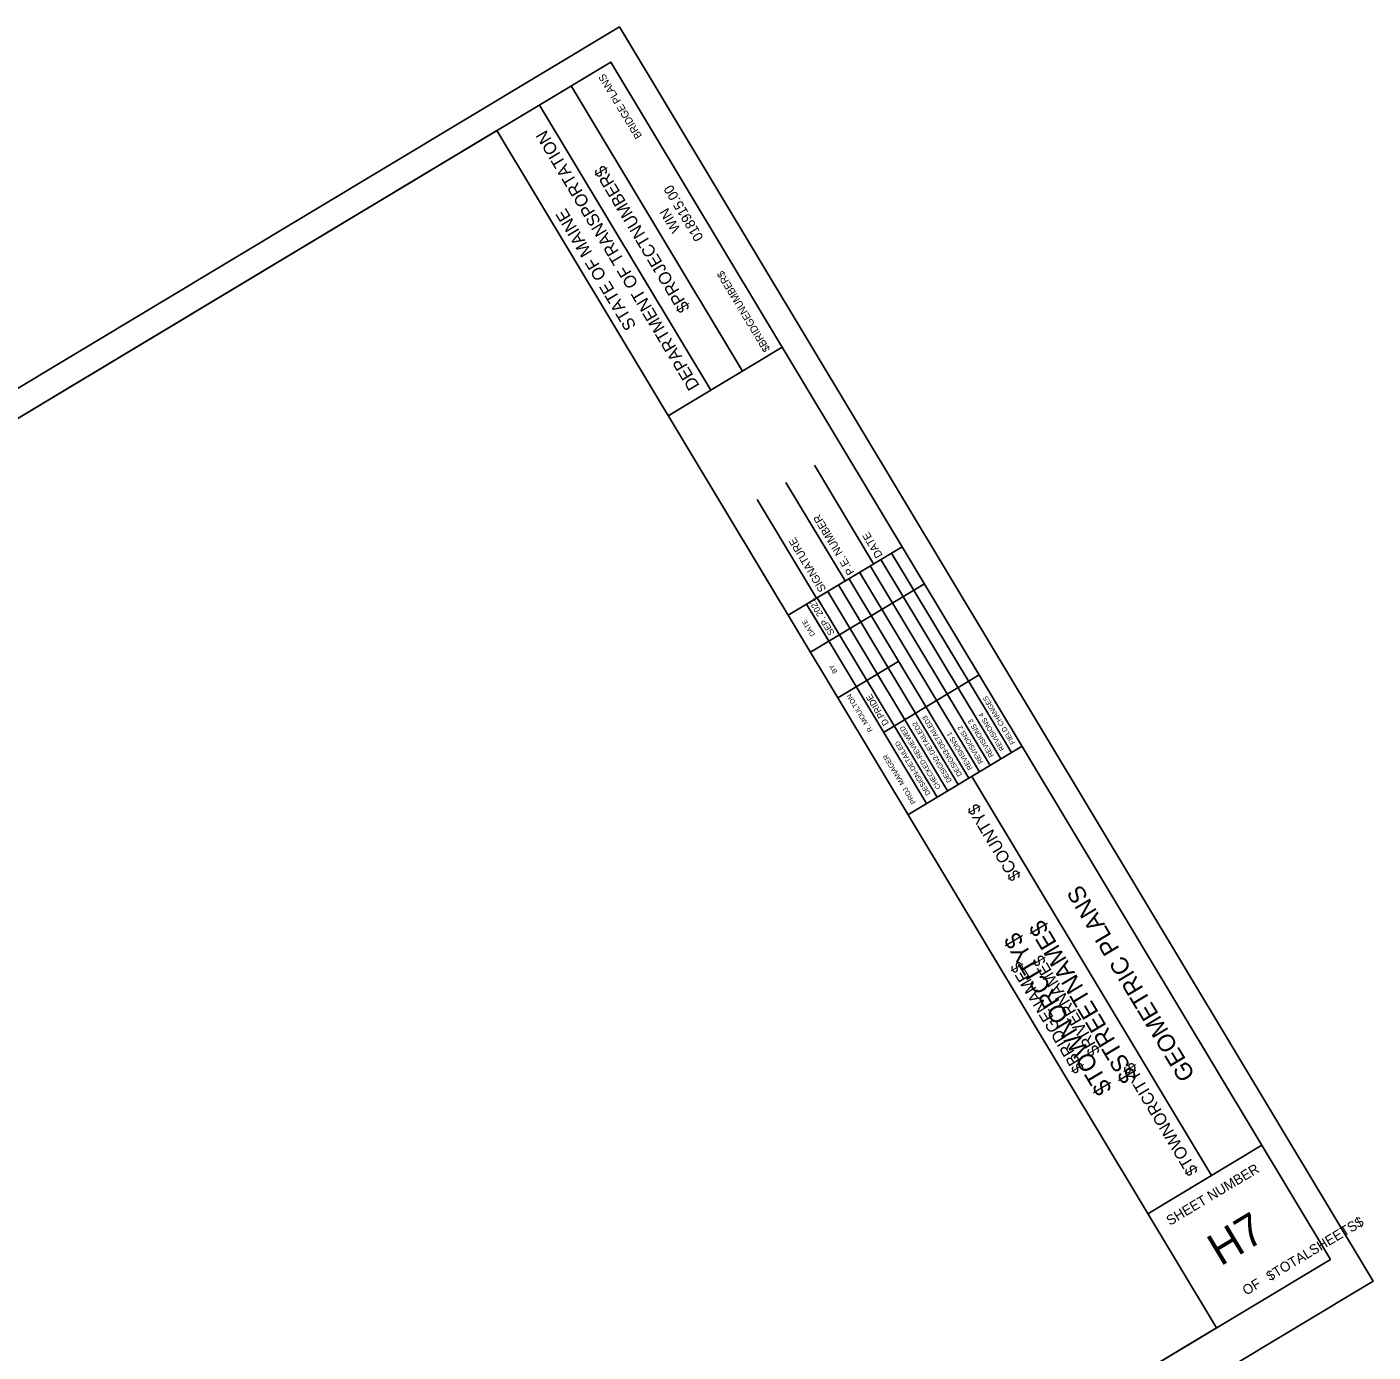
# Model space of a CAD drawing. Extents: x 1745684 to 1746696, y 463699 to 464609.
# Drawn here: x 1746190 to 1746696, y 464110 to 464609 of the extents above; entities that cross this region are included whole.
import ezdxf

# ---------------------------------------------------------------- set-up
doc = ezdxf.new("R2010")
doc.units = 0
for name, color, linetype in [('ANNOTATION', 7, 'Continuous'), ('D_Roadway_Centerline_Flags', 7, 'Continuous'), ('DIMENSIONS', 7, 'Continuous'), ('M_Fencing', 7, 'Continuous'), ('M_Misc_MiscItems', 7, 'Continuous')]:
    doc.layers.add(name, color=color, linetype=linetype)

msp = doc.modelspace()

# ---------------------------------------------------------------- linework, layer by layer
at = {"layer": 'DIMENSIONS'}
for p, q in [((1746459.05, 464479.19), (1746394.67, 464586.34)), ((1746447.07, 464471.99), (1746382.69, 464579.14)), ((1746637.1, 464119.54), (1746366.71, 464569.55)), ((1746431.1, 464462.38), (1746473.96, 464488.13)), ((1746508.29, 464406.73), (1746486.02, 464443.79)), ((1746497.57, 464400.29), (1746475.3, 464437.35)), ((1746486.86, 464393.85), (1746464.59, 464430.91)), ((1746476.14, 464387.41), (1746519, 464413.17)), ((1746521.21, 464312.41), (1746564.07, 464338.16)), ((1746635.3, 464176.81), (1746545.17, 464326.81)), ((1746611.34, 464162.41), (1746654.2, 464188.16))]:
    msp.add_line(p, q, dxfattribs=at)
msp.add_lwpolyline([(1745723.83, 464183.27), (1746409.56, 464595.3), (1746679.96, 464145.29), (1745994.22, 463733.26)], close=True, dxfattribs=at)
for points in [[(1746560.07, 464335.78), (1746515.01, 464410.77)], [(1746552.08, 464330.98), (1746507.03, 464405.97)], [(1746556.08, 464333.38), (1746511.02, 464408.37)], [(1746544.1, 464326.18), (1746499.04, 464401.17)], [(1746548.09, 464328.58), (1746503.03, 464403.57)], [(1746484.51, 464373.49), (1746527.37, 464399.24)], [(1746491.05, 464396.37), (1746536.11, 464321.38)], [(1746540.11, 464323.78), (1746495.05, 464398.77)], [(1746491.43, 464377.64), (1746483.06, 464391.57)], [(1746532.12, 464318.99), (1746487.06, 464393.97)], [(1746528.13, 464316.59), (1746484.89, 464388.55)], [(1746501.73, 464360.5), (1746517.71, 464370.1)], [(1746512.04, 464343.36), (1746547.97, 464364.95)], [(1746494.81, 464356.34), (1746501.74, 464360.5)]]:
    msp.add_lwpolyline(points, dxfattribs=at)
at = {"layer": 'M_Fencing'}
msp.add_lwpolyline([(1745967.42, 463699.31), (1746696.01, 464137.09), (1746412.74, 464608.53), (1745684.14, 464170.75)], close=True, dxfattribs=at)
at = {"layer": 'M_Misc_MiscItems'}
msp.add_lwpolyline([(1745723.83, 464183.27), (1746366.71, 464569.55), (1746637.1, 464119.54), (1745994.22, 463733.26)], close=True, dxfattribs=at)

# ---------------------------------------------------------------- texts
at = {"layer": 'ANNOTATION'}
for s, height, p in [('BRIDGE PLANS', 2.795, (1746421.34, 464567.52)), ('$BRIDGENUMBER$', 2.795, (1746469.49, 464487.4)), ('$COUNTY$', 4.536, (1746563.85, 464289.22)), ('$RIVERNAME$', 4.5358, (1746593.61, 464223.4)), ('$BRIDGENAME$', 4.5358, (1746587.75, 464216.88)), ('$TOWNORCITY$', 4.5358, (1746630.44, 464178.39))]:
    msp.add_text(s, height=height, rotation=121, dxfattribs=at).set_placement(p)
at = {"layer": 'D_Roadway_Centerline_Flags'}
for s, p in [('$STREETNAME$', (1746607.55, 464213.96)), ('$TOWNORCITY$', (1746598.14, 464209.35))]:
    msp.add_text(s, height=6.5214, rotation=121, dxfattribs=at).set_placement(p)
at = {"layer": 'DIMENSIONS'}
for s, height, rotation, p in [('DEPARTMENT OF TRANSPORTATION', 4.6588, 121, (1746443.01, 464473.69)), ('$PROJECTNUMBER$', 4.6588, 121, (1746439.4, 464502.86)), ('018915.00', 3.726, 121, (1746444.49, 464529.36)), ('STATE OF MAINE', 4.6588, 121, (1746419.26, 464496.2)), ('WIN', 3.726, 121, (1746435.84, 464532.52)), ('P.E. NUMBER', 2.9528, 121, (1746501.2, 464403.59)), ('SIGNATURE', 2.953, 121, (1746490.57, 464397.2)), ('DATE', 2.953, 121, (1746511.83, 464409.98)), ('SEP. 2021', 2.423, 121, (1746493.71, 464380.73)), ('DATE', 1.857, 121, (1746486.36, 464380.17)), ('BY', 1.857, 121, (1746494.78, 464366.15)), ('R. MOULTON', 1.864, 121, (1746508, 464344.15)), ('D.PRIDE', 2.423, 121, (1746514.11, 464346.78)), ('FIELD CHANGES', 1.8637, 121, (1746561.54, 464339.49)), ('REVISIONS 4', 1.8637, 121, (1746557.54, 464337.09)), ('CHECKED-REVIEWED', 1.8637, 121, (1746533.59, 464322.7)), ('DESIGN2-DETAILED2', 1.8637, 121, (1746537.74, 464325.19)), ('DESIGN3-DETAILED3', 1.8637, 121, (1746541.57, 464327.49)), ('REVISIONS 2', 1.8637, 121, (1746549.56, 464332.29)), ('REVISIONS 3', 1.8637, 121, (1746553.55, 464334.69)), ('DESIGN-DETAILED', 1.8637, 121, (1746529.75, 464320.39)), ('REVISIONS 1', 1.8637, 121, (1746545.56, 464329.89)), ('PROJ. MANAGER', 1.8637, 121, (1746524.26, 464317.09)), ('GEOMETRIC PLANS', 6.5214, 121, (1746629.34, 464214.64)), ('SHEET NUMBER', 3.7264, 31, (1746619.69, 464157.88)), ('H7', 12.097, 31, (1746638.68, 464142.55)), ('$TOTALSHEETS$', 3.7264, 31, (1746657.28, 464136.99)), ('OF', 3.726, 31, (1746648.32, 464131.6))]:
    msp.add_text(s, height=height, rotation=rotation, dxfattribs=at).set_placement(p)

doc.saveas('drawing.dxf')
